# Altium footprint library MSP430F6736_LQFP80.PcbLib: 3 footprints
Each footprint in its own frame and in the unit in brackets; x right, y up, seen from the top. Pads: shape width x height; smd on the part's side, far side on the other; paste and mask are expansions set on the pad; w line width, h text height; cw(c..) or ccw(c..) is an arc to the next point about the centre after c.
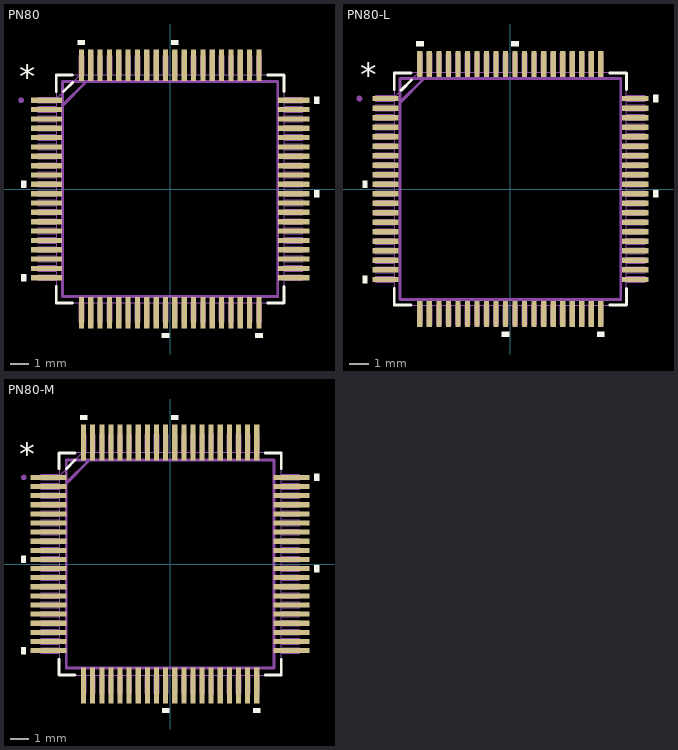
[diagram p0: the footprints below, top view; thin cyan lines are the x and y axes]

## PN80 [mil]
height 63
pads (80):
  rect 66x11 smd: 1(-260.5,187.01) 2(-260.5,167.32) 3(-260.5,147.64) 4(-260.5,127.95) 5(-260.5,108.27) 6(-260.5,88.58) 7(-260.5,68.9) 8(-260.5,49.21) 9(-260.5,29.53) 10(-260.5,9.84) 11(-260.5,-9.84) 12(-260.5,-29.53) 13(-260.5,-49.21) 14(-260.5,-68.9) 15(-260.5,-88.58) 16(-260.5,-108.27) 17(-260.5,-127.95) 18(-260.5,-147.64) 19(-260.5,-167.32) 20(-260.5,-187.01) 41(260.5,-187.01) 42(260.5,-167.32) 43(260.5,-147.64) 44(260.5,-127.95) 45(260.5,-108.27) 46(260.5,-88.58) 47(260.5,-68.9) 48(260.5,-49.21) 49(260.5,-29.53) 50(260.5,-9.84) 51(260.5,9.84) 52(260.5,29.53) 53(260.5,49.21) 54(260.5,68.9) 55(260.5,88.58) 56(260.5,108.27) 57(260.5,127.95) 58(260.5,147.64) 59(260.5,167.32) 60(260.5,187.01)
  rect 11x66 smd: 21(-187.01,-260.5) 22(-167.32,-260.5) 23(-147.64,-260.5) 24(-127.95,-260.5) 25(-108.27,-260.5) 26(-88.58,-260.5) 27(-68.9,-260.5) 28(-49.21,-260.5) 29(-29.53,-260.5) 30(-9.84,-260.5) 31(9.84,-260.5) 32(29.53,-260.5) 33(49.21,-260.5) 34(68.9,-260.5) 35(88.58,-260.5) 36(108.27,-260.5) 37(127.95,-260.5) 38(147.64,-260.5) 39(167.32,-260.5) 40(187.01,-260.5) 61(187.01,260.5) 62(167.32,260.5) 63(147.64,260.5) 64(127.95,260.5) 65(108.27,260.5) 66(88.58,260.5) 67(68.9,260.5) 68(49.21,260.5) 69(29.53,260.5) 70(9.84,260.5) 71(-9.84,260.5) 72(-29.53,260.5) 73(-49.21,260.5) 74(-68.9,260.5) 75(-88.58,260.5) 76(-108.27,260.5) 77(-127.95,260.5) 78(-147.64,260.5) 79(-167.32,260.5) 80(-187.01,260.5)
Top Overlay:
  region: -303.5,17.34 -313.5,17.34 -313.5,2.34 -303.5,2.34
  region: -303.5,-179.51 -313.5,-179.51 -313.5,-194.51 -303.5,-194.51
  region: -2.34,-303.5 -17.34,-303.5 -17.34,-313.5 -2.34,-313.5
  region: 194.51,-303.5 179.51,-303.5 179.51,-313.5 194.51,-313.5
  region: 303.5,-2.34 313.5,-2.34 313.5,-17.34 303.5,-17.34
  region: 303.5,194.51 313.5,194.51 313.5,179.51 303.5,179.51
  region: 17.34,303.5 2.34,303.5 2.34,313.5 17.34,313.5
  region: -179.51,303.5 -194.51,303.5 -194.51,313.5 -179.51,313.5
  lines w6: -240,-205.61 -240,-240 -205.61,-240 ; -240,205.61 -240,240 -205.61,240 ; -224.7,205.3 -205.3,224.7 ; 205.61,-240 240,-240 240,-205.61 ; 205.61,240 240,240 240,205.61
  text "*" at -318.5,211.85 h50
Mechanical 1:
  drawing of 335 lines, arcs and shapes, not listed
  text "63" at 0,0 h50
  text "*" at -318.5,211.85 h50

## PN80-L [mil]
height 63
pads (80):
  rect 54x11 smd: 1(-258.5,187.01) 2(-258.5,167.32) 3(-258.5,147.64) 4(-258.5,127.95) 5(-258.5,108.27) 6(-258.5,88.58) 7(-258.5,68.9) 8(-258.5,49.21) 9(-258.5,29.53) 10(-258.5,9.84) 11(-258.5,-9.84) 12(-258.5,-29.53) 13(-258.5,-49.21) 14(-258.5,-68.9) 15(-258.5,-88.58) 16(-258.5,-108.27) 17(-258.5,-127.95) 18(-258.5,-147.64) 19(-258.5,-167.32) 20(-258.5,-187.01) 41(258.5,-187.01) 42(258.5,-167.32) 43(258.5,-147.64) 44(258.5,-127.95) 45(258.5,-108.27) 46(258.5,-88.58) 47(258.5,-68.9) 48(258.5,-49.21) 49(258.5,-29.53) 50(258.5,-9.84) 51(258.5,9.84) 52(258.5,29.53) 53(258.5,49.21) 54(258.5,68.9) 55(258.5,88.58) 56(258.5,108.27) 57(258.5,127.95) 58(258.5,147.64) 59(258.5,167.32) 60(258.5,187.01)
  rect 11x54 smd: 21(-187.01,-258.5) 22(-167.32,-258.5) 23(-147.64,-258.5) 24(-127.95,-258.5) 25(-108.27,-258.5) 26(-88.58,-258.5) 27(-68.9,-258.5) 28(-49.21,-258.5) 29(-29.53,-258.5) 30(-9.84,-258.5) 31(9.84,-258.5) 32(29.53,-258.5) 33(49.21,-258.5) 34(68.9,-258.5) 35(88.58,-258.5) 36(108.27,-258.5) 37(127.95,-258.5) 38(147.64,-258.5) 39(167.32,-258.5) 40(187.01,-258.5) 61(187.01,258.5) 62(167.32,258.5) 63(147.64,258.5) 64(127.95,258.5) 65(108.27,258.5) 66(88.58,258.5) 67(68.9,258.5) 68(49.21,258.5) 69(29.53,258.5) 70(9.84,258.5) 71(-9.84,258.5) 72(-29.53,258.5) 73(-49.21,258.5) 74(-68.9,258.5) 75(-88.58,258.5) 76(-108.27,258.5) 77(-127.95,258.5) 78(-147.64,258.5) 79(-167.32,258.5) 80(-187.01,258.5)
Top Overlay:
  region: -295.5,17.34 -305.5,17.34 -305.5,2.34 -295.5,2.34
  region: -295.5,-179.51 -305.5,-179.51 -305.5,-194.51 -295.5,-194.51
  region: -2.34,-295.5 -17.34,-295.5 -17.34,-305.5 -2.34,-305.5
  region: 194.51,-295.5 179.51,-295.5 179.51,-305.5 194.51,-305.5
  region: 295.5,-2.34 305.5,-2.34 305.5,-17.34 295.5,-17.34
  region: 295.5,194.51 305.5,194.51 305.5,179.51 295.5,179.51
  region: 17.34,295.5 2.34,295.5 2.34,305.5 17.34,305.5
  region: -179.51,295.5 -194.51,295.5 -194.51,305.5 -179.51,305.5
  lines w6: -240,-205.61 -240,-240 -205.61,-240 ; -240,205.61 -240,240 -205.61,240 ; -225.73,204.27 -204.27,225.73 ; 205.61,-240 240,-240 240,-205.61 ; 205.61,240 240,240 240,205.61
  text "*" at -310.5,211.85 h50
Mechanical 1:
  drawing of 335 lines, arcs and shapes, not listed
  text "63" at 0,0 h50
  text "*" at -310.5,211.85 h50

## PN80-M [mil]
height 63
pads (80):
  rect 78x11 smd: 1(-262.5,187.01) 2(-262.5,167.32) 3(-262.5,147.64) 4(-262.5,127.95) 5(-262.5,108.27) 6(-262.5,88.58) 7(-262.5,68.9) 8(-262.5,49.21) 9(-262.5,29.53) 10(-262.5,9.84) 11(-262.5,-9.84) 12(-262.5,-29.53) 13(-262.5,-49.21) 14(-262.5,-68.9) 15(-262.5,-88.58) 16(-262.5,-108.27) 17(-262.5,-127.95) 18(-262.5,-147.64) 19(-262.5,-167.32) 20(-262.5,-187.01) 41(262.5,-187.01) 42(262.5,-167.32) 43(262.5,-147.64) 44(262.5,-127.95) 45(262.5,-108.27) 46(262.5,-88.58) 47(262.5,-68.9) 48(262.5,-49.21) 49(262.5,-29.53) 50(262.5,-9.84) 51(262.5,9.84) 52(262.5,29.53) 53(262.5,49.21) 54(262.5,68.9) 55(262.5,88.58) 56(262.5,108.27) 57(262.5,127.95) 58(262.5,147.64) 59(262.5,167.32) 60(262.5,187.01)
  rect 11x78 smd: 21(-187.01,-262.5) 22(-167.32,-262.5) 23(-147.64,-262.5) 24(-127.95,-262.5) 25(-108.27,-262.5) 26(-88.58,-262.5) 27(-68.9,-262.5) 28(-49.21,-262.5) 29(-29.53,-262.5) 30(-9.84,-262.5) 31(9.84,-262.5) 32(29.53,-262.5) 33(49.21,-262.5) 34(68.9,-262.5) 35(88.58,-262.5) 36(108.27,-262.5) 37(127.95,-262.5) 38(147.64,-262.5) 39(167.32,-262.5) 40(187.01,-262.5) 61(187.01,262.5) 62(167.32,262.5) 63(147.64,262.5) 64(127.95,262.5) 65(108.27,262.5) 66(88.58,262.5) 67(68.9,262.5) 68(49.21,262.5) 69(29.53,262.5) 70(9.84,262.5) 71(-9.84,262.5) 72(-29.53,262.5) 73(-49.21,262.5) 74(-68.9,262.5) 75(-88.58,262.5) 76(-108.27,262.5) 77(-127.95,262.5) 78(-147.64,262.5) 79(-167.32,262.5) 80(-187.01,262.5)
Top Overlay:
  region: -311.5,17.34 -321.5,17.34 -321.5,2.34 -311.5,2.34
  region: -311.5,-179.51 -321.5,-179.51 -321.5,-194.51 -311.5,-194.51
  region: -2.34,-311.5 -17.34,-311.5 -17.34,-321.5 -2.34,-321.5
  region: 194.51,-311.5 179.51,-311.5 179.51,-321.5 194.51,-321.5
  region: 311.5,-2.34 321.5,-2.34 321.5,-17.34 311.5,-17.34
  region: 311.5,194.51 321.5,194.51 321.5,179.51 311.5,179.51
  region: 17.34,311.5 2.34,311.5 2.34,321.5 17.34,321.5
  region: -179.51,311.5 -194.51,311.5 -194.51,321.5 -179.51,321.5
  lines w6: -240,-205.61 -240,-240 -205.61,-240 ; -240,205.61 -240,240 -205.61,240 ; -224.39,205.61 -205.61,224.39 ; 205.61,-240 240,-240 240,-205.61 ; 205.61,240 240,240 240,205.61
  text "*" at -326.5,211.85 h50
Mechanical 1:
  drawing of 335 lines, arcs and shapes, not listed
  text "63" at 0,0 h50
  text "*" at -326.5,211.85 h50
